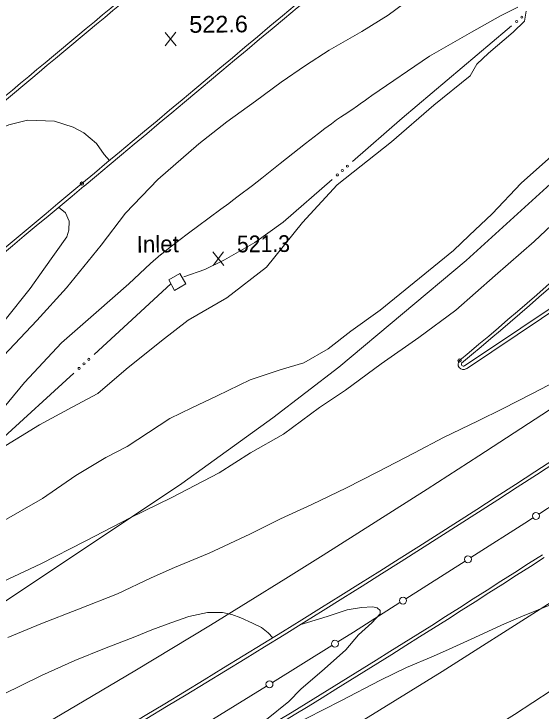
# Model space of a CAD drawing. Extents: x 2361284 to 2366480, y 6976556 to 6985346.
# Drawn here: x 2363734.5 to 2363886.1, y 6978761.2 to 6978961.5 of the extents above; entities that cross this region are included whole.
import ezdxf

# ---------------------------------------------------------------- set-up
doc = ezdxf.new("R2010")
doc.units = 0
doc.header["$LTSCALE"] = 1.9
doc.header["$PDMODE"] = 32
doc.header["$PDSIZE"] = 0.95
for name, color, linetype, lineweight in [('12', 7, 'Continuous', 13), ('13', 7, 'Continuous', 13), ('14', 7, 'Continuous', 13), ('21', 7, 'Continuous', 13), ('3', 7, 'Continuous', 13), ('5', 7, 'Continuous', 13), ('8', 7, 'Continuous', 13)]:
    doc.layers.add(name, color=color, linetype=linetype, lineweight=lineweight)

msp = doc.modelspace()

# ---------------------------------------------------------------- linework, layer by layer
at = {"layer": '12'}
for p, q in [((2363781.133, 6978952.322), (2363778.016, 6978956.173)), ((2363778.053, 6978952.293), (2363781.096, 6978956.202)), ((2363794.854, 6978889.249), (2363791.737, 6978893.1)), ((2363791.774, 6978889.22), (2363794.817, 6978893.129))]:
    msp.add_line(p, q, dxfattribs=at)
msp.add_lwpolyline([(2363892.818, 6978857.176), (2363883.613, 6978852.42), (2363874.964, 6978848.076), (2363867.946, 6978844.609), (2363858.052, 6978839.805), (2363849.642, 6978835.385), (2363838.916, 6978829.843), (2363830.137, 6978825.309), (2363820.183, 6978820.544), (2363811.161, 6978816.398), (2363802.382, 6978812.014), (2363790.665, 6978806.583), (2363780.663, 6978802.427), (2363774.01, 6978799.463), (2363764.313, 6978794.892), (2363753.115, 6978790.465), (2363742.244, 6978786.252), (2363732.741, 6978782.36)], dxfattribs=at)
at = {"layer": '13'}
for points in [[(2363885.671, 6978992.497), (2363881.4, 6978989.406), (2363876.317, 6978985.457), (2363869.48, 6978980.951), (2363864.349, 6978976.872), (2363857.057, 6978971.743), (2363850.935, 6978967.684), (2363842.067, 6978961.141), (2363834.501, 6978956.457), (2363825.192, 6978951.049), (2363818.324, 6978946.693), (2363811.338, 6978941.876), (2363803.96, 6978936.386), (2363795.756, 6978930.458), (2363787.675, 6978924.201), (2363775.872, 6978913.937), (2363766.573, 6978904.229), (2363759.651, 6978895.093), (2363749.687, 6978882.797), (2363741.135, 6978873.396), (2363728.274, 6978859.912)], [(2363730.279, 6978815.169), (2363742.751, 6978822.258), (2363752.299, 6978828.919), (2363760.991, 6978834.082), (2363767.06, 6978837.2), (2363779.316, 6978845.227), (2363785.656, 6978848.337), (2363792.994, 6978851.728), (2363802.421, 6978856.367), (2363811.023, 6978859.279), (2363817.866, 6978861.204), (2363824.897, 6978865.261), (2363831.369, 6978870.313), (2363839.844, 6978876.335), (2363860.871, 6978893.494), (2363865.39, 6978897.848), (2363871.952, 6978904.011), (2363880.358, 6978912.87), (2363893.409, 6978924.416), (2363909.787, 6978941.543), (2363925.709, 6978957.215), (2363929.332, 6978961.18), (2363932.562, 6978964.241)], [(2363879.378, 6978963.395), (2363874.421, 6978960.938), (2363866.035, 6978956.247), (2363853.949, 6978949.322), (2363837.457, 6978938.065)], [(2363729.622, 6978835.934), (2363741.93, 6978843.411), (2363751.273, 6978848.51), (2363758.676, 6978852.452), (2363766.839, 6978859.449), (2363776.993, 6978867.596), (2363784.607, 6978873.529), (2363795.737, 6978879.885), (2363807.154, 6978888.693), (2363817.462, 6978901.593), (2363827.469, 6978912.418), (2363843.043, 6978924.777), (2363855.243, 6978935.244), (2363865.634, 6978943.683), (2363867.543, 6978947.031), (2363870.923, 6978950.163), (2363878.045, 6978956.231), (2363881.325, 6978959.433), (2363881.808, 6978962.268)], [(2363837.457, 6978938.065), (2363836.345, 6978937.237), (2363835.6, 6978936.691), (2363834.099, 6978935.613), (2363833.292, 6978935.05), (2363831.659, 6978933.951), (2363829.468, 6978932.504), (2363828.378, 6978931.773), (2363827.3, 6978931.025), (2363826.766, 6978930.643), (2363825.815, 6978929.95), (2363823.924, 6978928.551), (2363822.046, 6978927.134), (2363820.801, 6978926.181), (2363818.327, 6978924.252), (2363811.11, 6978918.523), (2363805.753, 6978914.318), (2363803.068, 6978912.224), (2363799.029, 6978909.098), (2363797.373, 6978907.837), (2363796.263, 6978907.005), (2363794.032, 6978905.356), (2363787.308, 6978900.446), (2363785.081, 6978898.79), (2363783.974, 6978897.954), (2363781.488, 6978896.046), (2363779.839, 6978894.763), (2363776.559, 6978892.173)], [(2363762.04, 6978919.397), (2363760.523, 6978921.122), (2363758.273, 6978924.301), (2363754.614, 6978927.337), (2363751.518, 6978928.987), (2363746.231, 6978930.707), (2363738.457, 6978931.003), (2363733.041, 6978929.592), (2363727.075, 6978927.035), (2363721.184, 6978923.889), (2363712.329, 6978920.134)], [(2363732.064, 6978873.57), (2363739.237, 6978882.607), (2363743.115, 6978888.124), (2363749.728, 6978897.409), (2363750.29, 6978899.354), (2363750.415, 6978901.965), (2363749.352, 6978904.315), (2363747.397, 6978905.927)], [(2363890.699, 6978902.289), (2363884.078, 6978896.096), (2363872.86, 6978886.368), (2363861.514, 6978876.371), (2363850.878, 6978868.478), (2363840.14, 6978860.926), (2363829.8, 6978853.368), (2363822.368, 6978848.366), (2363811.999, 6978840.767), (2363802.54, 6978835.437), (2363793.544, 6978829.661), (2363779.722, 6978822.459), (2363768.164, 6978816.859), (2363754.989, 6978809.994), (2363742.299, 6978803.542), (2363729.766, 6978797.643)], [(2363776.797, 6978892.375), (2363773.801, 6978889.826), (2363767.556, 6978883.987), (2363758.185, 6978875.688), (2363748.188, 6978866.952), (2363737.554, 6978855.57), (2363729.853, 6978846.336)], [(2363952.621, 6978820.443), (2363948.345, 6978817.853), (2363941.146, 6978814.494), (2363936.197, 6978812.267), (2363930.411, 6978809.802), (2363920.336, 6978804.905), (2363913.389, 6978801.438), (2363904.085, 6978797.691), (2363898.617, 6978795.309), (2363889.687, 6978792.114), (2363880.213, 6978788.233), (2363874.635, 6978785.91), (2363867.008, 6978782.337), (2363859.66, 6978778.977), (2363855.148, 6978777.014), (2363847.339, 6978773.769), (2363839.854, 6978770.069), (2363828.458, 6978764.17), (2363818.686, 6978759.196), (2363802.476, 6978750.632), (2363788.101, 6978743.715)], [(2363801.186, 6978752.749), (2363804.128, 6978755.728), (2363807.129, 6978758.786), (2363813.531, 6978763.968), (2363817.008, 6978767.462), (2363823.851, 6978773.306), (2363829.95, 6978778.754), (2363833.619, 6978783.099), (2363837.448, 6978786.507), (2363839.853, 6978789.13), (2363839.784, 6978790.079), (2363838.966, 6978790.901), (2363837.573, 6978791.158), (2363834.444, 6978790.988), (2363830.351, 6978790.259), (2363824.608, 6978788.405), (2363816.762, 6978785.96)], [(2363808.966, 6978782.265), (2363807.572, 6978783.693), (2363805.728, 6978785.195), (2363803.105, 6978786.46), (2363799.781, 6978787.949), (2363797.201, 6978788.994), (2363794.465, 6978789.568), (2363790.155, 6978789.557), (2363784.806, 6978788.386), (2363779.653, 6978786.597), (2363774.132, 6978784.545), (2363769.311, 6978782.578), (2363760.603, 6978779.185), (2363752.025, 6978775.773), (2363742.465, 6978771.382), (2363731.337, 6978765.937)]]:
    msp.add_lwpolyline(points, dxfattribs=at)
at = {"layer": '14'}
for points in [[(2363949.629, 6978887.968), (2363929.935, 6978874.907), (2363890.416, 6978848.983), (2363868.159, 6978834.534), (2363853.276, 6978824.971), (2363823.411, 6978805.994), (2363812.654, 6978799.246), (2363791.042, 6978785.916), (2363769.312, 6978772.782), (2363754.767, 6978764.121), (2363725.557, 6978746.99), (2363693.768, 6978728.641), (2363677.819, 6978719.566), (2363653.804, 6978706.125), (2363629.648, 6978692.939), (2363617.507, 6978686.459), (2363544.112, 6978647.817), (2363507.33, 6978628.659), (2363367.402, 6978556.134), (2363223.565, 6978481.393), (2363026.986, 6978379.118)], [(2363951.494, 6978832.723), (2363916.041, 6978809.685), (2363857.621, 6978772.577), (2363781.115, 6978725.377), (2363714.322, 6978686.016), (2363680.485, 6978667.097), (2363570.079, 6978608.155), (2363462.054, 6978552.184), (2363320.548, 6978478.375), (2363145.373, 6978387.445), (2363047.939, 6978336.875)]]:
    msp.add_lwpolyline(points, dxfattribs=at)
at = {"layer": '21'}
for points in [[(2363877.518, 6978958.026), (2363876.267, 6978956.985), (2363846.139, 6978931.487), (2363831.896, 6978919.061)], [(2363825.985, 6978913.903), (2363811.921, 6978901.61), (2363803.816, 6978895.783), (2363795.073, 6978890.789), (2363789.369, 6978888.084), (2363783.409, 6978885.927)], [(2363779.628, 6978883.921), (2363767.285, 6978872.525), (2363757.57, 6978863.591)], [(2363751.78, 6978858.305), (2363730.463, 6978838.912), (2363707.311, 6978818.021)]]:
    msp.add_lwpolyline(points, dxfattribs=at)
for centre in [(2363879.051, 6978959.31), (2363880.524, 6978960.541), (2363830.387, 6978917.744), (2363827.495, 6978915.219), (2363828.94, 6978916.482), (2363754.677, 6978860.942), (2363756.092, 6978862.24), (2363753.257, 6978859.65)]:
    msp.add_circle(centre, 0.3, dxfattribs=at)
at = {"layer": '3'}
for p, q in [((2363754.677, 6978911.993), (2363754.676, 6978911.992)), ((2363863.223, 6978861.18), (2363863.302, 6978861.253))]:
    msp.add_line(p, q, dxfattribs=at)
for points in [[(2363011.072, 6978409.979), (2363168.573, 6978491.77), (2363368.216, 6978595.675), (2363555.651, 6978691.931), (2363594.46, 6978712.53), (2363671.163, 6978755.453), (2363729.15, 6978790.847), (2363782.829, 6978826.545), (2363808.985, 6978845.429), (2363827.885, 6978860.013), (2363864.479, 6978890.628), (2363923.502, 6978944.293), (2363947.382, 6978968.611)], [(2363864.046, 6978860.367), (2363864.047, 6978860.363), (2363929.067, 6978903.854)], [(2363864.582, 6978859.571), (2363864.584, 6978859.568), (2363929.605, 6978903.059)], [(2363952.175, 6978808.479), (2363878.438, 6978760.234), (2363806.248, 6978714.919), (2363769.733, 6978692.927), (2363684.374, 6978644.003), (2363641.063, 6978620.7), (2363500.405, 6978547.088), (2363379.13, 6978483.782), (2363259.87, 6978421.215), (2363142.44, 6978360.454), (2363059.726, 6978316.295)]]:
    msp.add_lwpolyline(points, dxfattribs=at)
for centre, radius, start, end in [((2311032.305, 7042034.271), 82243.01, 309.87005, 309.97478), ((2311032.306, 7042034.271), 82243.969, 309.87005, 309.97478), ((2391584.712, 6945589.747), 43449.604, 129.78045, 130.03943), ((2391584.712, 6945589.747), 43448.644, 129.78045, 130.03943), ((2363187.572, 6979677.578), 1058.761, 309.61119, 315.91924), ((2363187.572, 6979677.577), 1059.721, 309.61119, 315.91924), ((2378244.012, 6961509.003), 22646.156, 129.78, 130.14165), ((2378244.012, 6961509.003), 22645.196, 129.78, 130.14165), ((2361817.87, 6982011.643), 3793.856, 297.81552, 304.19799), ((2361817.87, 6982011.643), 3794.816, 297.81552, 304.19799), ((2363863.721, 6978860.85), 1.542, 136.03921, 303.95589), ((2363863.721, 6978860.85), 0.582, 136.03921, 303.95589), ((2361861.142, 6981945.89), 3736.294, 298.19355, 302.82403), ((2361861.142, 6981945.89), 3737.254, 298.19355, 302.82403)]:
    msp.add_arc(centre, radius, start, end, dxfattribs=at)
for p in [(2363754.062, 6978912.73), (2363862.611, 6978861.92)]:
    msp.add_point(p, dxfattribs=at)
at = {"layer": '5'}
for p, q in [((2363902.31, 6978828.725), (2363885.412, 6978817.794)), ((2363864.21, 6978804.271), (2363847.222, 6978793.47)), ((2363825.957, 6978780.046), (2363808.847, 6978769.444)), ((2363807.108, 6978768.367), (2363789.163, 6978757.245))]:
    msp.add_line(p, q, dxfattribs=at)
for points in [[(2363883.693, 6978816.678), (2363882.48, 6978815.896), (2363865.89, 6978805.338)], [(2363845.492, 6978792.373), (2363832.181, 6978783.897), (2363827.648, 6978781.092)]]:
    msp.add_lwpolyline(points, dxfattribs=at)
for centre in [(2363884.568, 6978817.247), (2363865.037, 6978804.801), (2363846.372, 6978792.929), (2363826.791, 6978780.562), (2363807.988, 6978768.91)]:
    msp.add_circle(centre, 1, dxfattribs=at)
at = {"layer": '8'}
msp.add_lwpolyline([(2363783.968, 6978883.943), (2363782.24, 6978886.886), (2363779.036, 6978885.136), (2363780.675, 6978882.072)], close=True, dxfattribs=at)

# ---------------------------------------------------------------- texts
at = {"layer": '12'}
for s, width, p in [('522.6', 1.05, (2363784.942, 6978956.046)), ('521.3', 0.95, (2363798.662, 6978892.973))]:
    msp.add_text(s, height=4.799, rotation=0.545, dxfattribs=dict(at, width=width)).set_placement(p)
at = {"layer": '8'}
msp.add_text('Inlet', height=4.799, rotation=0.545, dxfattribs=at).set_placement((2363769.842, 6978892.899))

doc.saveas('drawing.dxf')
